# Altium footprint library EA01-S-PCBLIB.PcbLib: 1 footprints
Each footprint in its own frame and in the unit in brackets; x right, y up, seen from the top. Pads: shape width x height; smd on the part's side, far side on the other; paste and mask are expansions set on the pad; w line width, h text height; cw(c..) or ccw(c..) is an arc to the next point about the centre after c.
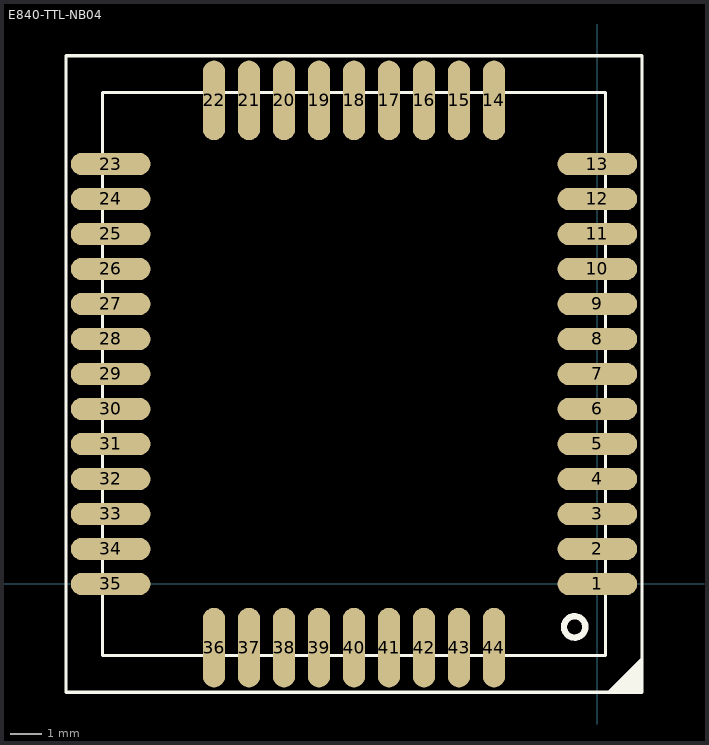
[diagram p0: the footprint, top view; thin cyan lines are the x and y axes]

## E840-TTL-NB04 [mm]
pads (44):
  oval 2.5x0.7 smd: 1(0,0) 2(0,1.1) 3(0,2.2) 4(0,3.3) 5(0,4.4) 6(0,5.5) 7(0,6.6) 8(0,7.7) 9(0,8.8) 10(0,9.9) 11(0,11) 12(0,12.1) 13(0,13.2) 23(-15.3,13.2) 24(-15.3,12.1) 25(-15.3,11) 26(-15.3,9.9) 27(-15.3,8.8) 28(-15.3,7.7) 29(-15.3,6.6) 30(-15.3,5.5) 31(-15.3,4.4) 32(-15.3,3.3) 33(-15.3,2.2) 34(-15.3,1.1) 35(-15.3,0)
  oval 0.7x2.5 smd: 14(-3.25,15.2) 15(-4.35,15.2) 16(-5.45,15.2) 17(-6.55,15.2) 18(-7.65,15.2) 19(-8.75,15.2) 20(-9.85,15.2) 21(-10.95,15.2) 22(-12.05,15.2) 36(-12.05,-2) 37(-10.95,-2) 38(-9.85,-2) 39(-8.75,-2) 40(-7.65,-2) 41(-6.55,-2) 42(-5.45,-2) 43(-4.35,-2) 44(-3.25,-2)
Top Overlay:
  circle w0.2: c-0.715,-1.35 r0.335
  region: 1.4,-2.35 1.4,-3.4 0.35,-3.4
  lines w0.1: 1.4,-3.4 -16.7,-3.4 -16.7,16.6 1.4,16.6 1.4,-3.4 ; 1.4,-3.4 0.35,-3.4 1.4,-2.35 1.4,-3.4 ; -15.55,-2.25 -15.55,15.45 0.25,15.45 0.25,-2.25 -15.55,-2.25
